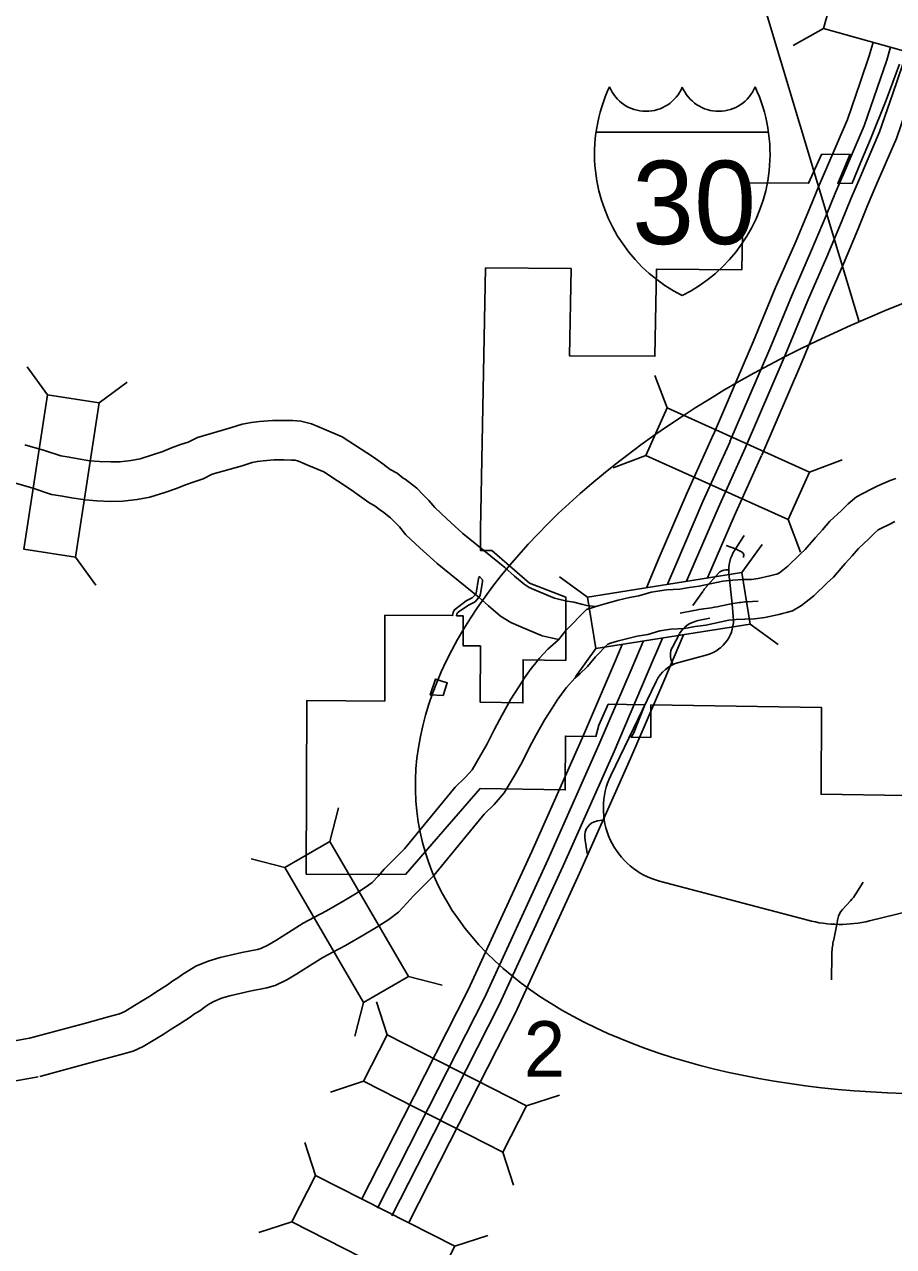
# Model space of a CAD drawing. Extents: x 813775 to 1157140, y 1757555 to 1979907.
# Drawn here: x 841416 to 854634, y 1925179 to 1943761 of the extents above; entities that cross this region are included whole.
import ezdxf

# ---------------------------------------------------------------- set-up
doc = ezdxf.new("R2010")
doc.units = 0
for name, color, linetype in [('1', 7, 'Continuous'), ('Level 10', 7, 'Continuous'), ('Level 19', 7, 'Continuous'), ('Level 20', 7, 'Continuous'), ('Level 23', 7, 'Continuous'), ('Level 6', 7, 'Continuous'), ('R_Draft', 7, 'Continuous')]:
    doc.layers.add(name, color=color, linetype=linetype)

msp = doc.modelspace()

# ---------------------------------------------------------------- linework, layer by layer
at = {"layer": '1'}
for p, q in [((852089, 1935837), (852230, 1935786)), ((852363, 1935989), (852216, 1935764)), ((852232, 1935789), (852329, 1935735)), ((852354, 1935683), (852350, 1935656)), ((852084, 1935469), (852128, 1935469)), ((851765, 1935183), (851970, 1935418)), ((852130, 1935411), (852177, 1934953)), ((851580, 1934928), (851731, 1935139)), ((851993, 1934917), (852165, 1934950)), ((852177, 1934953), (852196, 1934759)), ((852403, 1934982), (852574, 1934994)), ((851390, 1934810), (851594, 1934849)), ((851639, 1934691), (851841, 1934733)), ((851746, 1934875), (851822, 1934887)), ((851380, 1934498), (851271, 1934295)), ((851798, 1934178), (851370, 1934061)), ((851265, 1934060), (851280, 1934028)), ((851023, 1933772), (850334, 1932342)), ((850131, 1931651), (850234, 1931667)), ((849974, 1931155), (849940, 1931392)), ((854270, 1930132), (859688, 1931454)), ((851073, 1930737), (853330, 1930141)), ((854060, 1930540), (854173, 1930721)), ((853857, 1930302), (853979, 1930435)), ((853718, 1929822), (853770, 1930078)), ((853770, 1930078), (853787, 1930165)), ((853691, 1929235), (853695, 1929606))]:
    msp.add_line(p, q, dxfattribs=at)
for centre, radius, start, end in [((852673, 1935466), 546, 146.9006, 185.7832), ((852305, 1935692), 50, 350.1048, 60.9006), ((852083, 1935319), 150, 89.7131, 138.9731), ((852197, 1934807), 573, 138.9731, 144.4924), ((851254, 1938664), 3820, 278.5549, 281.1585), ((852534, 1933077), 1910, 93.9305, 101.1585), ((852314, 1931098), 3820, 98.5549, 100.8555), ((851653, 1934704), 546, 285.3262, 5.7832), ((851717, 1934317), 382, 101.6586, 151.6715), ((851500, 1934171), 260, 151.6715, 205.3846), ((851514, 1933535), 546, 105.3262, 154.2654), ((851366, 1931845), 1146, 154.2654, 255.2158), ((850167, 1931425), 229, 98.9178, 188.2311), ((853453, 1930920), 716, 317.3193, 327.9814), ((854068, 1930108), 286, 137.3193, 168.5678), ((853817, 1931988), 1910, 255.2158, 283.7123), ((854841, 1929594), 1146, 168.5678, 179.4066)]:
    msp.add_arc(centre, radius, start, end, dxfattribs=at)
at = {"layer": 'Level 10'}
for points in [[(846249, 1937491), (845973, 1937605), (845783, 1937691), (845621, 1937731), (845497, 1937737), (845365, 1937738), (845190, 1937740), (844993, 1937725), (844868, 1937711), (844726, 1937683), (844551, 1937626), (844050, 1937483)], [(841424, 1937368), (841723, 1937284), (841970, 1937201), (842096, 1937181), (842232, 1937157), (842411, 1937128), (842556, 1937117), (842731, 1937109), (842869, 1937111), (843039, 1937133), (843178, 1937158), (843363, 1937216), (843519, 1937270), (843652, 1937323), (843791, 1937372), (843904, 1937409), (844050, 1937483)], [(846249, 1937491), (846723, 1937181), (846864, 1937080), (846980, 1936996), (847085, 1936936), (847178, 1936864), (847204, 1936848), (847385, 1936711), (847486, 1936606), (847566, 1936523), (847657, 1936414), (847838, 1936242), (848084, 1936022), (848722, 1935506), (848869, 1935372), (849014, 1935249), (849090, 1935200), (849197, 1935155), (849476, 1935038), (849560, 1935019), (849669, 1934994), (849769, 1934977), (849907, 1934941), (849970, 1934928), (850103, 1934910)], [(845968, 1936957), (845734, 1937054), (845585, 1937122), (845534, 1937134), (845479, 1937137), (845359, 1937139), (845210, 1937140), (845048, 1937128), (844959, 1937118), (844878, 1937102), (844727, 1937052), (844270, 1936922)], [(845968, 1936957), (846384, 1936686), (846513, 1936593), (846653, 1936492), (846751, 1936435), (846837, 1936370), (846863, 1936354), (846985, 1936261), (847054, 1936189), (847118, 1936123), (847218, 1936003), (847431, 1935801), (847695, 1935565), (848331, 1935050), (848472, 1934922), (848657, 1934764), (848812, 1934667), (848964, 1934602), (849292, 1934464), (849428, 1934434), (849538, 1934409)], [(841263, 1936790), (841546, 1936711), (841827, 1936616), (841996, 1936590), (842131, 1936565), (842340, 1936532), (842519, 1936518), (842723, 1936508), (842914, 1936512), (843131, 1936540), (843321, 1936574), (843551, 1936646), (843728, 1936707), (843863, 1936761), (843984, 1936804), (844135, 1936853), (844270, 1936922)], [(849966, 1934868), (850155, 1934926), (850261, 1934959), (850445, 1935009), (850616, 1935048), (850761, 1935073), (850946, 1935128), (851182, 1935164), (851382, 1935175), (851523, 1935200), (851677, 1935221), (852038, 1935295), (852190, 1935310), (852346, 1935320), (852471, 1935323), (852573, 1935337), (852754, 1935377), (852811, 1935391), (852856, 1935401), (852861, 1935402), (852897, 1935423), (853024, 1935523), (853213, 1935708), (853290, 1935777), (853449, 1935961), (853554, 1936077), (853664, 1936208), (853841, 1936373), (853942, 1936474), (854069, 1936578), (854167, 1936629), (854295, 1936693), (854384, 1936740), (854476, 1936783), (854584, 1936829), (854669, 1936856)], [(850288, 1934339), (850331, 1934353), (850429, 1934383), (850590, 1934427), (850734, 1934459), (850898, 1934488), (851077, 1934541), (851244, 1934567), (851452, 1934578), (851616, 1934607), (851777, 1934629), (852129, 1934701), (852240, 1934712), (852373, 1934721), (852519, 1934724), (852677, 1934746), (852888, 1934792), (852947, 1934806), (853006, 1934819), (853097, 1934846), (853234, 1934925), (853420, 1935071), (853624, 1935270), (853720, 1935356), (853898, 1935563), (854006, 1935682), (854100, 1935795), (854257, 1935941), (854345, 1936028), (854402, 1936075), (854440, 1936095), (854569, 1936159), (854652, 1936203)], [(841492, 1928346), (842329, 1928573), (842708, 1928675), (842862, 1928717), (842942, 1928754), (843092, 1928843), (843208, 1928914), (843306, 1928977), (843455, 1929072), (843594, 1929161), (843673, 1929219), (843751, 1929264), (843824, 1929321), (843914, 1929379), (844025, 1929444), (844209, 1929521), (844392, 1929574), (844723, 1929648), (844961, 1929695), (845012, 1929710), (845119, 1929762), (845241, 1929835), (845431, 1929957), (845657, 1930097), (845826, 1930186), (846008, 1930282), (846273, 1930436), (846449, 1930543), (846615, 1930648), (846706, 1930716), (846794, 1930809), (846887, 1930915), (847197, 1931225), (847967, 1932162), (848125, 1932314), (848223, 1932428), (848359, 1932656), (848452, 1932824), (848563, 1933047), (848675, 1933252), (848814, 1933500), (848934, 1933689), (849022, 1933825), (849124, 1933967), (849191, 1934056), (849250, 1934124), (849305, 1934186), (849377, 1934260), (849459, 1934331), (849537, 1934405), (849652, 1934546), (849966, 1934868)], [(841649, 1927767), (842485, 1927993), (842866, 1928096), (843069, 1928152), (843221, 1928223), (843400, 1928328), (843528, 1928405), (843631, 1928473), (843778, 1928566), (843936, 1928667), (844002, 1928716), (844084, 1928763), (844170, 1928830), (844229, 1928868), (844295, 1928906), (844411, 1928955), (844541, 1928993), (844846, 1929061), (845103, 1929112), (845229, 1929148), (845406, 1929235), (845557, 1929325), (845751, 1929450), (845954, 1929576), (846105, 1929654), (846300, 1929757), (846580, 1929921), (846765, 1930033), (846956, 1930154), (847105, 1930265), (847238, 1930404), (847326, 1930506), (847642, 1930822), (848407, 1931753), (848562, 1931901), (848713, 1932078), (848879, 1932357), (848983, 1932545), (849095, 1932770), (849199, 1932961), (849330, 1933193), (849440, 1933367), (849517, 1933487), (849608, 1933612), (849658, 1933679), (849699, 1933727), (849744, 1933776), (849789, 1933823), (849863, 1933887), (849978, 1933997), (850100, 1934147), (850288, 1934339)], [(839266, 1927454), (839508, 1927561), (839668, 1927644), (839783, 1927709), (839953, 1927821), (840139, 1927946), (840305, 1928042), (840493, 1928133), (840767, 1928217), (841518, 1928352)], [(839508, 1926905), (839767, 1927019), (839954, 1927116), (840097, 1927197), (840285, 1927321), (840457, 1927437), (840586, 1927512), (840712, 1927572), (840909, 1927633), (841624, 1927761)]]:
    msp.add_lwpolyline(points, dxfattribs=at)
at = {"layer": 'Level 19'}
for points in [[(851894, 1937527), (852501, 1938935), (852840, 1939759), (853136, 1940436), (853356, 1940960), (853500, 1941315), (853632, 1941621), (853932, 1942318), (854125, 1942880), (854270, 1943300), (854325, 1943490)], [(852146, 1937419), (852754, 1938828), (853093, 1939651), (853388, 1940328), (853610, 1940855), (853753, 1941208), (853884, 1941512), (854189, 1942218), (854385, 1942790), (854532, 1943217), (854589, 1943414)], [(852376, 1937320), (852985, 1938731), (853323, 1939554), (853618, 1940229), (853841, 1940759), (853984, 1941112), (854114, 1941413), (854422, 1942128), (854621, 1942709), (854770, 1943141), (854829, 1943345)], [(852629, 1937211), (853238, 1938624), (853576, 1939446), (853871, 1940121), (854095, 1940654), (854238, 1941006), (854366, 1941305), (854679, 1942029), (854881, 1942620), (855032, 1943058), (855097, 1943279)], [(850874, 1935197), (851068, 1935655), (851484, 1936617), (851897, 1937533)], [(851196, 1935253), (851321, 1935547), (851735, 1936506), (852147, 1937420)], [(851487, 1935298), (851551, 1935448), (851964, 1936405), (852375, 1937318)], [(851806, 1935347), (852216, 1936294), (852626, 1937205)], [(846783, 1925765), (847419, 1927011), (848413, 1928963), (849380, 1931072), (850154, 1932808), (850659, 1933983), (850827, 1934380)], [(847005, 1925648), (847641, 1926897), (848638, 1928855), (849608, 1930969), (850383, 1932708), (850889, 1933885), (851119, 1934428)], [(847255, 1925533), (847886, 1926772), (848886, 1928735), (849859, 1930855), (850635, 1932598), (851142, 1933777), (851440, 1934481)], [(846542, 1925897), (847174, 1927136), (848166, 1929083), (849130, 1931185), (849902, 1932918), (850406, 1934091), (850507, 1934331)]]:
    msp.add_lwpolyline(points, dxfattribs=at)
at = {"layer": 'Level 20'}
for p, q in [((853567, 1943701), (853106, 1943442)), ((841768, 1938130), (841456, 1938556)), ((842551, 1938010), (842977, 1938322)), ((851191, 1937930), (851004, 1938423)), ((851191, 1937930), (850865, 1937207)), ((853357, 1936954), (851191, 1937930)), ((850865, 1937207), (850372, 1937020)), ((850865, 1937207), (853032, 1936232)), ((853357, 1936954), (853851, 1937141)), ((853032, 1936232), (853357, 1936954)), ((853032, 1936232), (853219, 1935738)), ((852327, 1935427), (852637, 1935854)), ((842190, 1935662), (842503, 1935236)), ((849981, 1935053), (849553, 1935363)), ((852327, 1935427), (849981, 1935053)), ((852452, 1934645), (852327, 1935427)), ((849981, 1935053), (850105, 1934271)), ((850105, 1934271), (852452, 1934645)), ((852452, 1934645), (852879, 1934335)), ((850105, 1934271), (849795, 1933844)), ((846060, 1931340), (846194, 1931851)), ((845376, 1930941), (844865, 1931075)), ((847258, 1929288), (847768, 1929154)), ((846574, 1928889), (846440, 1928378)), ((846932, 1928397), (846769, 1928900)), ((846573, 1927692), (846070, 1927528)), ((849049, 1927319), (849551, 1927482)), ((845844, 1926262), (845681, 1926764)), ((848690, 1926613), (848853, 1926111)), ((845484, 1925556), (844982, 1925393)), ((847961, 1925183), (848463, 1925346))]:
    msp.add_line(p, q, dxfattribs=at)
for points in [[(853567, 1943701), (855854, 1943059), (856068, 1943821), (853781, 1944463)], [(841768, 1938130), (841408, 1935782), (842190, 1935662), (842551, 1938010)], [(845376, 1930941), (846574, 1928889), (847258, 1929288), (846060, 1931340)], [(849049, 1927319), (846932, 1928397), (846573, 1927692), (848690, 1926613)], [(847961, 1925183), (845844, 1926262), (845484, 1925556), (847601, 1924477)]]:
    msp.add_lwpolyline(points, close=True, dxfattribs=at)
at = {"layer": 'Level 23'}
msp.add_line((850110, 1942123), (852732, 1942123), dxfattribs=at)
for centre, radius, start, end in [((852546, 1941782), 2460, 155.2204, 185.7928), ((850868, 1943039), 599, 202.1459, 337.3414), ((851974, 1943039), 599, 202.6586, 337.8541), ((850295, 1941782), 2460, 354.2072, 24.7796), ((852501, 1941802), 2417, 186.3923, 243.4571), ((850341, 1941802), 2417, 296.5429, 353.6077)]:
    msp.add_arc(centre, radius, start, end, dxfattribs=at)
at = {"layer": 'Level 6'}
msp.add_lwpolyline([(854814, 1932040), (853531, 1932057), (853539, 1933374), (850944, 1933415), (850941, 1932920), (850642, 1932925), (850678, 1932980), (850850, 1933416), (850295, 1933425), (850153, 1933106), (850108, 1932937), (849644, 1932941), (849642, 1932122), (848345, 1932143), (847209, 1930836), (845701, 1930842), (845711, 1933484), (846895, 1933472), (846899, 1934779), (847927, 1934772), (847927, 1934774), (847930, 1934796), (847934, 1934818), (847944, 1934843), (847954, 1934863), (848135, 1934998), (848226, 1935045), (848229, 1935047), (848285, 1935111), (848288, 1935115), (848323, 1935339), (848336, 1935366), (848382, 1935315), (848380, 1935290), (848350, 1935106), (848344, 1935068), (848270, 1934983), (848167, 1934931), (848014, 1934826), (848000, 1934814), (847995, 1934803), (847991, 1934793), (847990, 1934786), (847987, 1934774), (847987, 1934771), (848087, 1934771), (848086, 1934315), (848350, 1934313), (848348, 1933456), (848997, 1933446), (848999, 1934102), (849648, 1934092), (849650, 1934748), (849651, 1935053), (849096, 1935266), (848526, 1935761), (848354, 1935762), (848354, 1936081), (848429, 1940060), (849729, 1940050), (849704, 1938724), (851004, 1938715), (851028, 1940040), (852327, 1940031), (852351, 1941355), (853341, 1941347), (853537, 1941785), (853973, 1941787), (853786, 1941344), (854005, 1941347), (854129, 1941657), (854285, 1942015), (854521, 1942612), (854723, 1943158)], dxfattribs=at)
msp.add_lwpolyline([(847783, 1933556), (847847, 1933753), (847666, 1933808), (847587, 1933567)], close=True, dxfattribs=at)
at = {"layer": 'R_Draft'}
msp.add_line((854111, 1939240), (843306, 1975221), dxfattribs=at)
msp.add_ellipse((858856, 1934247), major_axis=(11387, 2926), ratio=0.533954, dxfattribs=at)

# ---------------------------------------------------------------- texts
at = {"layer": 'Level 20'}
msp.add_text('2', height=845, dxfattribs=at).set_placement((849010, 1927761))
at = {"layer": 'Level 23'}
msp.add_text('30', height=1267.2, dxfattribs=at).set_placement((850658, 1940422))

doc.saveas('drawing.dxf')
